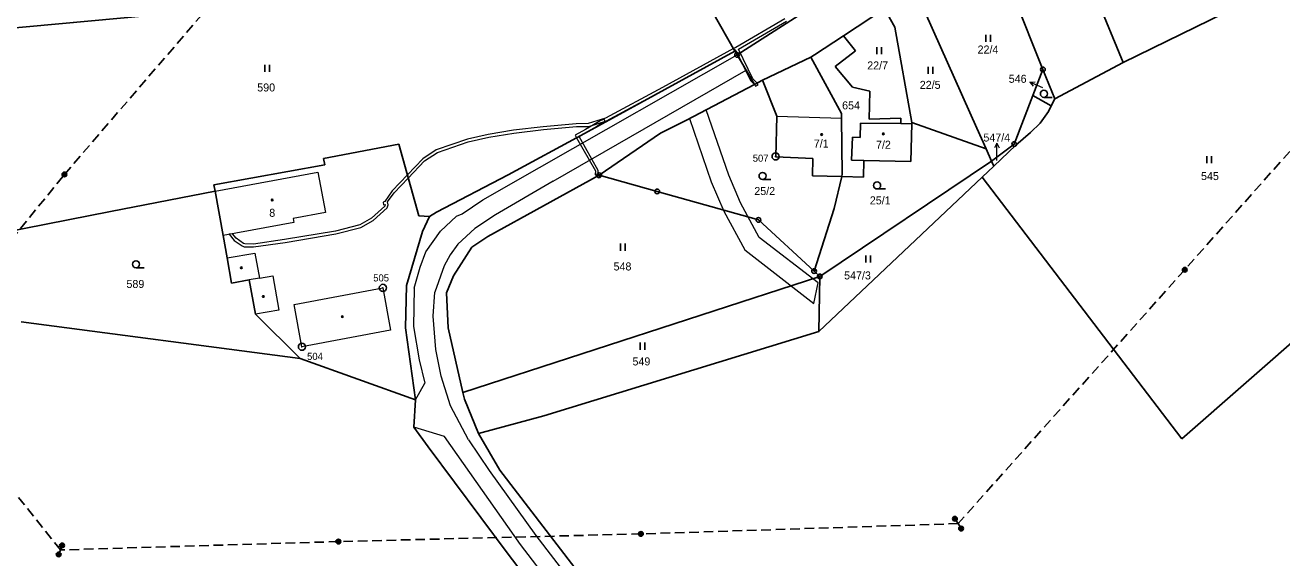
# Model space of a CAD drawing. Extents: x -653193 to -651624, y -1092017 to -1090260.
# Drawn here: x -652826.7 to -652559.8, y -1091426.8 to -1091313.6 of the extents above; entities that cross this region are included whole.
import ezdxf
from ezdxf.enums import TextEntityAlignment as Align

# ---------------------------------------------------------------- set-up
doc = ezdxf.new("R2010")
doc.units = 0
doc.header["$LTSCALE"] = 0.68
doc.linetypes.add('MEDIUM_DASHED', pattern=[4.5, 3, -1.5])
for name, color, linetype, lineweight in [('1', 7, 'Continuous', 25), ('13', 7, 'Continuous', 13), ('3', 7, 'Continuous', 25), ('4', 7, 'Continuous', 13), ('5', 7, 'Continuous', 25), ('6', 7, 'Continuous', 25), ('7', 7, 'Continuous', 13), ('8', 7, 'Continuous', 25)]:
    doc.layers.add(name, color=color, linetype=linetype, lineweight=lineweight)
doc.layers.add('2', color=7, linetype='Continuous')

msp = doc.modelspace()

# ---------------------------------------------------------------- linework, layer by layer
at = {"layer": '1'}
for p, q in [((-652675.52, -1091319.87), (-652618.24, -1091283.07)), ((-652606.63, -1091289.65), (-652593.47, -1091321.5)), ((-652610.54, -1091322.98), (-652620.82, -1091297.26)), ((-652637.81, -1091305.85), (-652624.61, -1091335.43)), ((-652652.89, -1091315.8), (-652644.23, -1091310.07)), ((-652593.47, -1091321.5), (-652565.79, -1091307.87)), ((-652800.34, -1091311.51), (-652854.02, -1091316.45)), ((-652680.76, -1091310.76), (-652675.98, -1091319.08)), ((-652659.06, -1091319.87), (-652652.89, -1091315.8)), ((-652652.89, -1091315.8), (-652650.34, -1091318.98)), ((-652675.98, -1091319.08), (-652707.9, -1091336.57)), ((-652675.98, -1091319.08), (-652675.52, -1091319.87)), ((-652673.59, -1091323.15), (-652675.52, -1091319.87)), ((-652659.86, -1091320.35), (-652670.11, -1091325.22)), ((-652659.06, -1091319.87), (-652659.86, -1091320.35)), ((-652650.34, -1091318.98), (-652654.67, -1091322.37)), ((-652673.59, -1091323.15), (-652671.8, -1091326.19)), ((-652654.67, -1091322.37), (-652650.97, -1091326.74)), ((-652612.67, -1091328.53), (-652610.54, -1091322.98)), ((-652610.54, -1091322.98), (-652608.05, -1091329.19)), ((-652608.05, -1091329.19), (-652593.47, -1091321.5)), ((-652670.11, -1091325.22), (-652671.8, -1091326.19)), ((-652667.05, -1091332.88), (-652670.11, -1091325.22)), ((-652671.8, -1091326.19), (-652686.24, -1091333.72)), ((-652647.31, -1091327.56), (-652650.97, -1091326.74)), ((-652647.46, -1091333.53), (-652647.31, -1091327.56)), ((-652608.81, -1091330.72), (-652609.38, -1091331.92)), ((-652608.05, -1091329.19), (-652608.81, -1091330.72)), ((-652686.24, -1091333.72), (-652691.76, -1091336.53)), ((-652667.31, -1091341.54), (-652667.05, -1091332.88)), ((-652653.31, -1091333.34), (-652653.17, -1091345.16)), ((-652647.46, -1091333.53), (-652640.71, -1091333.35)), ((-652640.73, -1091334.49), (-652640.71, -1091333.35)), ((-652609.38, -1091331.92), (-652611.11, -1091334.37)), ((-652707.9, -1091336.57), (-652724.14, -1091345.37)), ((-652691.76, -1091336.53), (-652704.79, -1091345.44)), ((-652649.34, -1091337.4), (-652649.27, -1091334.36)), ((-652649.27, -1091334.36), (-652640.73, -1091334.49)), ((-652640.73, -1091334.49), (-652638.38, -1091334.52)), ((-652638.38, -1091334.52), (-652638.62, -1091342.56)), ((-652622.63, -1091339.86), (-652638.43, -1091334.25)), ((-652638.43, -1091334.25), (-652638.38, -1091334.52)), ((-652624.61, -1091335.43), (-652622.63, -1091339.86)), ((-652613.19, -1091336.34), (-652616.29, -1091339.03)), ((-652611.11, -1091334.37), (-652613.19, -1091336.34)), ((-652747.37, -1091338.86), (-652763.37, -1091341.88)), ((-652743.15, -1091354.06), (-652747.37, -1091338.86)), ((-652651.18, -1091342.28), (-652651.02, -1091337.36)), ((-652651.02, -1091337.36), (-652649.34, -1091337.4)), ((-652621.46, -1091342.48), (-652616.63, -1091338.82)), ((-652616.29, -1091339.03), (-652621, -1091343.52)), ((-652763.37, -1091341.88), (-652763.11, -1091343.23)), ((-652659.44, -1091341.9), (-652667.31, -1091341.54)), ((-652659.48, -1091345.58), (-652659.44, -1091341.9)), ((-652622.63, -1091339.86), (-652621.46, -1091342.48)), ((-652763.11, -1091343.23), (-652786.64, -1091347.46)), ((-652657.95, -1091366.94), (-652621.46, -1091342.48)), ((-652648.57, -1091342.34), (-652651.18, -1091342.28)), ((-652648.57, -1091342.34), (-652648.68, -1091345.88)), ((-652638.62, -1091342.56), (-652648.57, -1091342.34)), ((-652621, -1091343.52), (-652623.44, -1091345.84)), ((-652621.46, -1091342.48), (-652621, -1091343.52)), ((-652786.64, -1091347.46), (-652786.41, -1091348.83)), ((-652724.14, -1091345.37), (-652739.38, -1091353.31)), ((-652704.79, -1091345.44), (-652728.48, -1091358.46)), ((-652704.79, -1091345.44), (-652692.48, -1091348.9)), ((-652653.3, -1091345.74), (-652659.48, -1091345.58)), ((-652658.14, -1091378.63), (-652623.44, -1091345.84)), ((-652653.3, -1091345.74), (-652654.91, -1091352.5)), ((-652653.17, -1091345.16), (-652653.3, -1091345.74)), ((-652648.68, -1091345.88), (-652653.3, -1091345.74)), ((-652623.44, -1091345.84), (-652581.06, -1091401.45)), ((-652808.58, -1091353.15), (-652786.41, -1091348.83)), ((-652786.41, -1091348.83), (-652784.71, -1091358.24)), ((-652670.99, -1091354.94), (-652692.48, -1091348.9)), ((-652659.15, -1091365.83), (-652654.91, -1091352.5)), ((-652831.25, -1091357.64), (-652808.58, -1091353.15)), ((-652740.85, -1091354.25), (-652743.15, -1091354.06)), ((-652740.85, -1091354.25), (-652742.33, -1091357.4)), ((-652739.38, -1091353.31), (-652740.85, -1091354.25)), ((-652659.15, -1091365.83), (-652670.99, -1091354.94)), ((-652742.33, -1091357.4), (-652745.74, -1091368.86)), ((-652581.06, -1091401.45), (-652530.45, -1091357.14)), ((-652784.71, -1091358.24), (-652783.83, -1091363.02)), ((-652731.84, -1091360.71), (-652735.73, -1091366.84)), ((-652728.48, -1091358.46), (-652731.84, -1091360.71)), ((-652783.83, -1091363.02), (-652782.88, -1091368.37)), ((-652657.95, -1091366.94), (-652659.15, -1091365.83)), ((-652782.88, -1091368.37), (-652779.13, -1091367.7)), ((-652779.13, -1091367.7), (-652777.84, -1091374.98)), ((-652745.74, -1091368.86), (-652745.98, -1091377.86)), ((-652735.73, -1091366.84), (-652737.22, -1091370.43)), ((-652733.75, -1091391.63), (-652657.95, -1091366.94)), ((-652658.14, -1091378.63), (-652657.95, -1091366.94)), ((-652737.22, -1091370.43), (-652736.92, -1091377.88)), ((-652768.36, -1091384.4), (-652827.61, -1091376.61)), ((-652777.84, -1091374.98), (-652768.36, -1091384.4)), ((-652745.98, -1091377.86), (-652743.83, -1091393.21)), ((-652736.92, -1091377.88), (-652733.75, -1091391.63)), ((-652716.55, -1091396.59), (-652658.14, -1091378.63)), ((-652768.36, -1091384.4), (-652743.83, -1091393.21)), ((-652733.43, -1091393.04), (-652733.75, -1091391.63)), ((-652743.83, -1091393.21), (-652744.19, -1091398.97)), ((-652730.46, -1091400.31), (-652733.43, -1091393.04)), ((-652730.46, -1091400.31), (-652716.55, -1091396.59)), ((-652741.17, -1091403.19), (-652744.19, -1091398.97)), ((-652725.9, -1091408.1), (-652730.46, -1091400.31)), ((-652741.17, -1091403.19), (-652724.32, -1091425.66)), ((-652689.47, -1091455.61), (-652725.9, -1091408.1)), ((-652724.32, -1091425.66), (-652697.11, -1091461.71))]:
    msp.add_line(p, q, dxfattribs=at)
for points in [[(-652644.23, -1091310.07), (-652642.03, -1091313.97), (-652638.43, -1091334.25)], [(-652659.86, -1091320.35), (-652653.31, -1091332.35), (-652653.31, -1091333.34)], [(-652616.63, -1091338.82), (-652612.67, -1091328.53), (-652608.81, -1091330.72)]]:
    msp.add_lwpolyline(points, dxfattribs=at)
at = {"layer": '13'}
msp.add_lwpolyline([(-652665.38, -1091312.2), (-652675.79, -1091318.27), (-652676.29, -1091318.54), (-652675.77, -1091318.94), (-652672.65, -1091325.33), (-652671.8, -1091326.19), (-652671.27, -1091325.89), (-652672.15, -1091324.99), (-652675.25, -1091318.65), (-652665.02, -1091312.68)], dxfattribs=at)
for points in [[(-652781.92, -1091358.85), (-652782.7, -1091357.88), (-652783.38, -1091358), (-652782.34, -1091359.29), (-652780.64, -1091360.46), (-652780.2, -1091360.65), (-652778.22, -1091360.68), (-652771.52, -1091359.71), (-652760.73, -1091357.93), (-652755.41, -1091356.58), (-652752.79, -1091355.07), (-652749.84, -1091352.35), (-652749.65, -1091351.77), (-652749.76, -1091351.09), (-652748.34, -1091349.16), (-652745.38, -1091346.04), (-652741.9, -1091342.39), (-652739.16, -1091340.62), (-652732.63, -1091338.37), (-652728.26, -1091337.37), (-652722.96, -1091336.48), (-652716.66, -1091335.75), (-652709.64, -1091335.11), (-652707.02, -1091335.08), (-652703.26, -1091333.9), (-652691.08, -1091327.33), (-652675.99, -1091319.06), (-652676.29, -1091318.54), (-652691.36, -1091326.81), (-652703.5, -1091333.34), (-652707.12, -1091334.48), (-652709.68, -1091334.51), (-652716.72, -1091335.15), (-652723.04, -1091335.88), (-652728.38, -1091336.79), (-652732.79, -1091337.79), (-652739.42, -1091340.08), (-652742.28, -1091341.93), (-652745.56, -1091345.38), (-652748.8, -1091348.78), (-652750.37, -1091351.06), (-652750.72, -1091351.14), (-652750.61, -1091351.74), (-652750.26, -1091351.66), (-652750.36, -1091352.01), (-652753.15, -1091354.59), (-652755.63, -1091356.02), (-652760.85, -1091357.35), (-652771.62, -1091359.11), (-652778.26, -1091360.08), (-652780.08, -1091360.05), (-652780.34, -1091359.94)], [(-652671.05, -1091326.24), (-652671.24, -1091325.92), (-652671.27, -1091325.89), (-652671.8, -1091326.19), (-652671.77, -1091326.21), (-652671.58, -1091326.53)], [(-652703.77, -1091333.51), (-652704.62, -1091333.9), (-652706, -1091334.76), (-652707.71, -1091335.73), (-652709.93, -1091336.93), (-652709.61, -1091337.5), (-652709.08, -1091337.21), (-652707.41, -1091336.25), (-652705.7, -1091335.28), (-652704.34, -1091334.42), (-652703.53, -1091334.05)], [(-652658.27, -1091368.35), (-652670.79, -1091358.68), (-652674.77, -1091351.35), (-652677.28, -1091345.43), (-652682.06, -1091331.54), (-652685.65, -1091333.41), (-652681.02, -1091346.87), (-652678.36, -1091353.09), (-652673.9, -1091361.33), (-652659.19, -1091372.68)], [(-652709.61, -1091337.5), (-652705.61, -1091344.55), (-652705.66, -1091345.27), (-652705.29, -1091345.71), (-652704.79, -1091345.44), (-652705.04, -1091345.09), (-652705.01, -1091344.41), (-652709.08, -1091337.21)], [(-652705.29, -1091345.71), (-652705.02, -1091346.03), (-652704.63, -1091345.77), (-652704.79, -1091345.44)]]:
    msp.add_lwpolyline(points, close=True, dxfattribs=at)
at = {"layer": '3'}
for p, q in [((-652622.661, -1091317.09), (-652622.661, -1091315.59)), ((-652621.66, -1091317.09), (-652621.66, -1091315.59)), ((-652645.841, -1091319.72), (-652645.841, -1091318.22)), ((-652644.84, -1091319.72), (-652644.84, -1091318.22)), ((-652775.821, -1091323.5), (-652775.821, -1091322)), ((-652774.82, -1091323.5), (-652774.82, -1091322)), ((-652634.941, -1091323.89), (-652634.941, -1091322.39)), ((-652633.94, -1091323.89), (-652633.94, -1091322.39)), ((-652610.343, -1091328.9), (-652608.593, -1091328.9)), ((-652575.751, -1091342.89), (-652575.751, -1091341.39)), ((-652574.75, -1091342.89), (-652574.75, -1091341.39)), ((-652670.103, -1091346.35), (-652668.353, -1091346.35)), ((-652645.773, -1091348.37), (-652644.023, -1091348.37)), ((-652700.261, -1091361.49), (-652700.261, -1091359.99)), ((-652699.26, -1091361.49), (-652699.26, -1091359.99)), ((-652648.201, -1091364.01), (-652648.201, -1091362.51)), ((-652647.2, -1091364.01), (-652647.2, -1091362.51)), ((-652803.193, -1091365.12), (-652801.443, -1091365.12)), ((-652696.101, -1091382.53), (-652696.101, -1091381.03)), ((-652695.1, -1091382.53), (-652695.1, -1091381.03))]:
    msp.add_line(p, q, dxfattribs=at)
for centre in [(-652610.3429, -1091328.1498), (-652670.1029, -1091345.5998), (-652645.7729, -1091347.6198), (-652803.1929, -1091364.3698)]:
    msp.add_circle(centre, 0.75, dxfattribs=at)
at = {"layer": '4'}
for p, q in [((-652717.49, -1091343.8), (-652675.52, -1091319.87)), ((-652714.56, -1091346.73), (-652673.59, -1091323.15)), ((-652667.05, -1091332.88), (-652653.31, -1091333.34)), ((-652786.41, -1091348.83), (-652764.58, -1091344.77)), ((-652764.58, -1091344.77), (-652762.92, -1091353.36)), ((-652729.51, -1091350.71), (-652717.49, -1091343.8)), ((-652714.56, -1091346.73), (-652726.83, -1091353.83)), ((-652733.9, -1091353.64), (-652729.51, -1091350.71)), ((-652769.65, -1091355.52), (-652784.71, -1091358.24)), ((-652762.92, -1091353.36), (-652769.82, -1091354.61)), ((-652769.82, -1091354.61), (-652769.65, -1091355.52)), ((-652738.49, -1091357.32), (-652735.13, -1091354.13)), ((-652735.13, -1091354.13), (-652733.9, -1091353.64)), ((-652726.83, -1091353.83), (-652731.25, -1091356.76)), ((-652741.65, -1091361.73), (-652738.49, -1091357.32)), ((-652731.25, -1091356.76), (-652734.84, -1091360.09)), ((-652734.84, -1091360.09), (-652736.46, -1091362.4)), ((-652783.83, -1091363.02), (-652777.95, -1091361.98)), ((-652777.95, -1091361.98), (-652776.97, -1091367.32)), ((-652742.83, -1091364.97), (-652741.65, -1091361.73)), ((-652736.46, -1091362.4), (-652737.75, -1091364.68)), ((-652744.09, -1091369.42), (-652742.83, -1091364.97)), ((-652737.75, -1091364.68), (-652739.71, -1091370.28)), ((-652776.97, -1091367.32), (-652779.13, -1091367.7)), ((-652776.97, -1091367.32), (-652774.14, -1091366.82)), ((-652774.14, -1091366.82), (-652772.85, -1091374.1)), ((-652769.58, -1091372.9), (-652750.76, -1091369.38)), ((-652750.76, -1091369.38), (-652749.16, -1091378.35)), ((-652744.09, -1091369.42), (-652744.24, -1091377.58)), ((-652740.1, -1091375.38), (-652739.71, -1091370.28)), ((-652772.85, -1091374.1), (-652777.84, -1091374.98)), ((-652767.96, -1091381.9), (-652769.58, -1091372.9)), ((-652739.53, -1091382.48), (-652740.1, -1091375.38)), ((-652749.16, -1091378.35), (-652767.96, -1091381.9)), ((-652744.24, -1091377.58), (-652743.08, -1091384.7)), ((-652743.08, -1091384.7), (-652741.86, -1091389.67)), ((-652738.39, -1091388.12), (-652739.53, -1091382.48)), ((-652743.83, -1091393.21), (-652741.86, -1091389.67)), ((-652736.41, -1091394.47), (-652738.39, -1091388.12)), ((-652732.54, -1091401.65), (-652736.41, -1091394.47)), ((-652737.67, -1091400.99), (-652744.19, -1091398.97)), ((-652721.52, -1091423.91), (-652737.67, -1091400.99)), ((-652732.54, -1091401.65), (-652728.21, -1091408.18)), ((-652728.21, -1091408.18), (-652718.25, -1091421.99)), ((-652718.25, -1091421.99), (-652691.2, -1091457.11)), ((-652694.28, -1091459.48), (-652721.52, -1091423.91))]:
    msp.add_line(p, q, dxfattribs=at)
at = {"layer": '5'}
for centre in [(-652657.5368, -1091336.8092), (-652644.4368, -1091336.6692), (-652774.2568, -1091350.6992), (-652780.8268, -1091365.1192), (-652776.1568, -1091371.2192), (-652759.3668, -1091375.4892)]:
    msp.add_circle(centre, 0.175, dxfattribs=at)
at = {"layer": '6', "linetype": 'MEDIUM_DASHED'}
for p, q in [((-652818.4, -1091345.29), (-652786.9, -1091308.66)), ((-652531.73, -1091310.63), (-652580.43, -1091365.53)), ((-652850.92, -1091385.26), (-652818.4, -1091345.29)), ((-652580.43, -1091365.53), (-652628.57, -1091419.49)), ((-652819.26, -1091425.08), (-652850.92, -1091385.26)), ((-652628.57, -1091419.49), (-652695.93, -1091421.67)), ((-652628.57, -1091419.49), (-652629.23, -1091418.44)), ((-652628.57, -1091419.49), (-652627.92, -1091420.53)), ((-652695.93, -1091421.67), (-652760.21, -1091423.3)), ((-652760.21, -1091423.3), (-652819.26, -1091425.08)), ((-652819.26, -1091425.08), (-652818.91, -1091424.13)), ((-652819.62, -1091426.03), (-652819.26, -1091425.08))]:
    msp.add_line(p, q, dxfattribs=at)
at = {"layer": '6'}
for centre, radius in [((-652818.4034, -1091345.2899), 0.5), ((-652818.4034, -1091345.2899), 0.4), ((-652818.4034, -1091345.2899), 0.3), ((-652818.4034, -1091345.2899), 0.2), ((-652818.4034, -1091345.2899), 0.1), ((-652580.4334, -1091365.5299), 0.5), ((-652580.4334, -1091365.5299), 0.4), ((-652580.4334, -1091365.5299), 0.3), ((-652580.4334, -1091365.5299), 0.2), ((-652580.4334, -1091365.5299), 0.1), ((-652629.2334, -1091418.4399), 0.5), ((-652629.2334, -1091418.4399), 0.4), ((-652629.2334, -1091418.4399), 0.3), ((-652629.2334, -1091418.4399), 0.2), ((-652629.2334, -1091418.4399), 0.1), ((-652695.9334, -1091421.6699), 0.5), ((-652695.9334, -1091421.6699), 0.4), ((-652695.9334, -1091421.6699), 0.3), ((-652695.9334, -1091421.6699), 0.2), ((-652695.9334, -1091421.6699), 0.1), ((-652627.9234, -1091420.5299), 0.5), ((-652627.9234, -1091420.5299), 0.4), ((-652627.9234, -1091420.5299), 0.3), ((-652627.9234, -1091420.5299), 0.2), ((-652627.9234, -1091420.5299), 0.1), ((-652818.9134, -1091424.1299), 0.5), ((-652818.9134, -1091424.1299), 0.4), ((-652818.9134, -1091424.1299), 0.3), ((-652818.9134, -1091424.1299), 0.2), ((-652818.9134, -1091424.1299), 0.1), ((-652760.2134, -1091423.2999), 0.5), ((-652760.2134, -1091423.2999), 0.4), ((-652760.2134, -1091423.2999), 0.3), ((-652760.2134, -1091423.2999), 0.2), ((-652760.2134, -1091423.2999), 0.1), ((-652819.6234, -1091426.0299), 0.5), ((-652819.6234, -1091426.0299), 0.4), ((-652819.6234, -1091426.0299), 0.3), ((-652819.6234, -1091426.0299), 0.2), ((-652819.6234, -1091426.0299), 0.1)]:
    msp.add_circle(centre, radius, dxfattribs=at)
at = {"layer": '7'}
for p, q in [((-652613.332, -1091325.677), (-652612.606, -1091326.53)), ((-652620.35, -1091338.609), (-652620.851, -1091339.61))]:
    msp.add_line(p, q, dxfattribs=at)
for points in [[(-652610.57, -1091326.85), (-652613.332, -1091325.677), (-652612.215, -1091325.608)], [(-652620.35, -1091342.3), (-652620.35, -1091341.61), (-652620.35, -1091338.609), (-652619.849, -1091339.61)]]:
    msp.add_lwpolyline(points, dxfattribs=at)
at = {"layer": '8'}
for centre, radius in [((-652675.52, -1091319.8699), 0.5), ((-652675.52, -1091319.8699), 0.0303), ((-652610.54, -1091322.9799), 0.5), ((-652610.54, -1091322.9799), 0.0303), ((-652616.63, -1091338.8199), 0.5), ((-652616.63, -1091338.8199), 0.0303), ((-652667.34, -1091341.4598), 0.75), ((-652667.34, -1091341.4598), 0.03), ((-652704.79, -1091345.4399), 0.5), ((-652704.79, -1091345.4399), 0.0303), ((-652692.48, -1091348.8999), 0.5), ((-652692.48, -1091348.8999), 0.0303), ((-652670.99, -1091354.9399), 0.5), ((-652670.99, -1091354.9399), 0.0303), ((-652659.15, -1091365.8299), 0.5), ((-652659.15, -1091365.8299), 0.0303), ((-652750.76, -1091369.3798), 0.75), ((-652657.95, -1091366.9399), 0.5), ((-652657.95, -1091366.9399), 0.0303), ((-652750.76, -1091369.3798), 0.03), ((-652767.96, -1091381.8998), 0.75), ((-652767.96, -1091381.8998), 0.03)]:
    msp.add_circle(centre, radius, dxfattribs=at)

# ---------------------------------------------------------------- texts
at = {"layer": '2'}
for s, p in [('22/4', (-652622.219, -1091319.585)), ('22/7', (-652645.659, -1091322.965)), ('590', (-652775.549, -1091327.645)), ('22/5', (-652634.499, -1091327.095)), ('654', (-652651.309, -1091331.455)), ('547/4', (-652620.35, -1091338.285)), ('7/1', (-652657.64, -1091339.565)), ('7/2', (-652644.43, -1091339.815)), ('545', (-652575.069, -1091346.475)), ('25/2', (-652669.649, -1091349.655)), ('25/1', (-652645.109, -1091351.645)), ('8', (-652774.26, -1091354.285)), ('548', (-652699.859, -1091365.685)), ('547/3', (-652649.94, -1091367.595)), ('589', (-652803.329, -1091369.405)), ('549', (-652695.839, -1091385.865))]:
    msp.add_text(s, height=1.7, dxfattribs=at).set_placement(p, align=Align.CENTER)
msp.add_text('546', height=1.7, dxfattribs=at).set_placement((-652614.019, -1091325.805), align=Align.RIGHT)
at = {"layer": '8'}
for s, p in [('507', (-652668.839, -1091342.577)), ('505', (-652749.456, -1091368.02)), ('504', (-652763.506, -1091384.688))]:
    msp.add_text(s, height=1.5, dxfattribs=at).set_placement(p, align=Align.RIGHT)

doc.saveas('drawing.dxf')
